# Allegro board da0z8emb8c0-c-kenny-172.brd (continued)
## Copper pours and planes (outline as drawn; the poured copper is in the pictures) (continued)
L_SPK+_1 on BOTTOM (solid shape): 116.31,22.34 116.41,22.29 116.52,22.27 116.54,22.27 116.62,22.25 116.65,22.17 116.65,20.41 116.37,20.13 116.37,19.55 116.22,19.4 115.34,19.4 115.22,19.52 115.22,20.3 115.91,20.99 115.91,22.23 116.02,22.34
L_SPK- on TOP (solid shape): 117.26,17.76 117.26,16.61 117.11,16.46 116.22,16.46 116.11,16.57 116.11,17.82 116.18,17.89 117.12,17.89
L_SPK- on IN2 (solid shape): 117.24,16.91 117.24,15.52 117.05,15.33 116.19,15.33 116.05,15.46 116.05,16.84 116.24,17.02 117.14,17.02
L_SPK- on IN2 (solid shape): 202.06,21.57 202.06,19.65 201.89,19.48 200.3,19.48 200.17,19.62 200.17,19.97 200.66,20.46 201.01,20.46 201.21,20.67 201.21,20.67 201.27,20.73 201.27,21.52 201.37,21.62 202,21.62
L_SPK-_1 on TOP (solid shape): 117.04,21.32 117.16,21.28 117.28,21.27 117.4,21.28 117.52,21.32 117.53,21.32 117.66,21.32 117.79,21.2 117.79,20.36 117.66,20.23 117.66,19.5 117.35,19.2 117.35,18.52 117.23,18.4 116.37,18.4 116.26,18.51 116.26,19.18 116.52,19.44 116.52,20.16 116.82,20.46 116.82,21.11 117.03,21.32
L_SPK-_1 on BOTTOM (solid shape): 117.08,22.33 117.18,22.29 117.28,22.27 117.39,22.29 117.49,22.33 117.5,22.34 117.61,22.34 117.66,22.29 117.66,19.49 117.47,19.29 116.69,19.29 116.56,19.42 116.56,19.97 116.94,20.35 116.94,22.26 117.02,22.34 117.07,22.34
LDO_3V3 on IN2 (solid shape): 17.79,13.02 17.79,11.85 17.56,11.63 15.31,11.63 13.99,12.94 13.99,14.31 14.19,14.51 16.3,14.51
MBCLK on TOP (solid shape): 103.97,22.21 103.97,21.65 103.8,21.47 103.21,21.47 103.01,21.27 102.13,21.27 102.01,21.4 102.01,21.98 102.05,22.03 102.6,22.03 102.84,22.27 102.84,22.54 103.09,22.79 103.39,22.79
MBCLK on BOTTOM (solid shape): 103.98,23.26 103.98,22.89 103.35,22.26 103.09,22.26 102.94,22.41 102.94,22.62 103.31,22.99 103.31,23.31 103.34,23.35 103.89,23.35
MBDATA on TOP (solid shape): 106.88,22.1 106.88,20.84 106.8,20.76 106.15,20.76 105.84,20.44 105.27,20.44 105.13,20.58 105.13,21.21 105.3,21.38 105.3,22.39 105.6,22.69 106.3,22.69
MVREFDA on TOP (solid shape): 118.97,101.49 118.97,101.36 118.96,101.34 118.78,101.13 118.72,100.87 118.74,100.73 118.79,100.59 118.8,100.56 118.79,100.53 118.69,100.44 117.87,100.44 117.87,100.44 117.87,101.16 117.88,101.2 117.92,101.21 118.24,101.21 118.53,101.5 118.96,101.5
MVREFDB on TOP (solid shape): 114.3,97.78 114.88,97.78 115.22,97.44 115.22,96.85 114.31,95.94 114.14,95.94 114.1,95.97 114.1,97.82 114.11,97.83 114.25,97.83
ODD_PRSNT#_C on BOTTOM (solid shape): 133.5,17.98 133.5,16.85 133.48,16.77 133.47,16.69 133.48,16.62 133.5,16.54 133.5,15.76 133.01,15.27 127.4,15.27 126.94,15.73 125.31,15.73 124.7,15.12 123.98,15.12 123.87,15.23 123.87,15.65 123.99,15.77 124.29,15.77 124.4,15.88 124.4,17.19 124.54,17.34 127.49,17.34 127.88,16.95 127.89,16.91 127.88,16.9 127.83,16.8 127.82,16.69 127.93,16.42 128.2,16.31 128.34,16.34 128.46,16.41 128.52,16.44 128.85,16.31 129.18,16.44 129.24,16.41 129.36,16.34 129.5,16.31 129.77,16.42 129.88,16.69 129.88,16.7 129.9,16.73 129.93,16.75 133.01,16.75 133.26,17 133.26,17.99 133.29,18.02 133.46,18.02
PBA_PWR on BOTTOM (solid shape): 52.56,22.72 52.56,20.76 52.34,20.53 50.79,20.53 49.95,21.37 49.95,22.62 50.11,22.78 51.2,22.78 51.29,22.69 51.29,22.24 51.42,22.11 52.03,22.11 52.13,22.21 52.13,22.69 52.26,22.82 52.46,22.82
PBA_PWR_C on BOTTOM (solid shape): 56.38,22.08 56.44,22.07 56.49,22.07 56.54,22.07 56.59,22.08 57.01,22.08 57.08,22.01 57.08,21.66 57.03,21.55 57.02,21.43 57.02,20.85 57.03,20.73 57.08,20.61 57.08,20.18 56.96,20.05 56.07,20.05 55.94,20.18 55.94,21.96 56.07,22.08
PBA_PWR_R on BOTTOM (solid shape): 53.4,22.44 53.4,22.13 53.55,21.98 55.46,21.98 55.64,21.8 55.64,20.15 55.39,19.91 55.37,19.9 55.34,19.9 55.26,19.92 55.18,19.93 55.02,19.9 54.87,19.82 53.58,19.82 53.35,19.59 52.77,19.59 52.73,19.61 52.72,19.65 52.72,20.56 52.82,20.66 52.82,22.74 52.83,22.78 52.87,22.8 53.05,22.8
R_SPK+ on TOP (solid shape): 120.22,17.75 120.22,16.53 120.13,16.44 118.85,16.44 118.7,16.59 118.7,17.79 118.8,17.89 120.08,17.89
R_SPK+ on IN2 (solid shape): 120.91,17.56 120.91,16.65 120.87,16.62 118.78,16.62 118.74,16.66 118.74,17.55 118.81,17.63 120.84,17.63
R_SPK+ on IN2 (solid shape): outline of 105 points within 195.67,19.39 200.96,22.04
R_SPK+_1 on TOP (solid shape): 119.02,21.35 119.16,21.29 119.31,21.27 119.38,21.27 119.46,21.25 119.49,21.17 119.49,20.81 119.53,20.65 119.62,20.51 119.93,20.2 119.93,20.18 120.03,19.9 120.29,19.75 120.31,19.73 120.31,18.51 120.25,18.44 119.12,18.44 119,18.55 119,19.24 119.16,19.4 119.16,19.93 118.93,20.16 118.93,21.32 118.97,21.36 119,21.36
R_SPK+_1 on BOTTOM (solid shape): 118.97,22.25 119.01,22.27 119.04,22.26 119.31,22.17 119.59,22.26 119.62,22.27 119.66,22.25 119.82,22.08 119.82,21.89 119.82,21.87 119.72,21.55 119.82,21.22 119.82,21.21 119.82,21.13 120.28,20.67 120.28,19.41 120.28,19.39 120.27,19.37 120.18,19.29 119.3,19.29 119.19,19.4 119.19,20.42 118.81,20.8 118.81,22.08
R_SPK- on TOP (solid shape): 118.54,17.83 118.54,16.6 118.42,16.48 117.52,16.48 117.4,16.6 117.4,17.8 117.49,17.89 118.47,17.89
R_SPK- on IN2 (solid shape): 118.53,18.87 118.53,16.63 118.52,16.62 117.48,16.62 117.4,16.7 117.4,18.85 117.53,18.99 118.41,18.99
R_SPK- on IN2 (solid shape): 202.46,23.76 202.46,22.05 202.35,21.94 201.64,21.94 201.34,22.25 201.34,22.86 200.81,23.39 200.81,24.1 201.07,24.36 201.86,24.36
R_SPK-_1 on TOP (solid shape): 118.05,21.32 118.17,21.28 118.3,21.27 118.42,21.28 118.54,21.32 118.55,21.32 118.68,21.2 118.68,20.02 118.94,19.77 118.94,19.47 118.72,19.25 118.72,18.54 118.58,18.4 117.77,18.4 117.66,18.51 117.66,19.28 117.8,19.42 117.8,20.21 117.92,20.32 117.92,21.2 118.04,21.32
R_SPK-_1 on BOTTOM (solid shape): 118.1,22.33 118.19,22.29 118.3,22.27 118.4,22.29 118.5,22.33 118.51,22.34 118.55,22.34 118.68,22.21 118.68,20.47 118.91,20.24 118.91,19.43 118.78,19.29 117.9,19.29 117.79,19.41 117.79,20.3 117.92,20.43 117.92,22.21 118.04,22.34 118.08,22.34
RING2 on BOTTOM (solid shape): 210.45,35.46 210.45,34.35 210.39,34.3 209.36,34.3 209.24,34.41 209.24,35.47 209.35,35.57 210.34,35.57
RING2 on BOTTOM (solid shape): 214.07,40.5 214.07,39.32 214.02,39.28 212.63,39.28 212.56,39.35 211.97,39.35 211.85,39.47 211.85,39.55 213.96,39.55 213.96,39.75 212.66,39.75 212.66,39.55 211.85,39.55 211.85,40.05 213.96,40.05 213.96,40.25 212.66,40.25 212.66,40.05 211.85,40.05 211.85,40.42 211.98,40.55 214.02,40.55
RING2 on BOTTOM (solid shape): 203.21,31.44 203.21,31.15 203.1,31.04 202.78,31.04 202.6,30.86 202.6,30.79 202.58,30.73 202.58,30.67 202.58,30.6 202.6,30.55 202.6,30.46 202.63,30.43 202.63,29.33 202.58,29.28 202.46,29.28 202.44,29.31 202.44,30.27 202.04,30.66 202.04,31.52 202.07,31.55 202.42,31.55 202.6,31.73 202.92,31.73
RING2 on IN1 (solid shape): outline of 282 points within 201.95,30.71 212.64,40.86
SENSEA on BOTTOM (solid shape): 200.8,32.31 200.89,32.21 200.89,31.85 200.66,31.62 200.66,30.84 200.98,30.53 200.98,30.51 201,30.39 201.04,30.28 201.04,29.31 200.97,29.24 200.89,29.24 200.19,29.94 200.19,30.28 200.13,30.59 199.95,30.85 199.77,31.03 199.77,31.97 199.77,31.97 199.77,32.28 199.8,32.31 200.8,32.31
SLEEVE on BOTTOM (solid shape): 210.49,34.04 210.49,33.25 210.37,33.13 209.4,33.13 209.29,33.23 209.29,34.12 209.3,34.14 210.4,34.14
SLEEVE on BOTTOM (solid shape): 212.41,39.04 213.99,39.04 214.02,39.01 214.02,38.75 212.66,38.75 212.66,38.55 214.02,38.55 214.02,38.25 212.66,38.25 212.66,38.05 214.02,38.05 214.02,37.82 213.95,37.75 212.52,37.75 212.29,37.97 212,37.97 211.88,38.1 211.88,39.02 211.95,39.09 212.36,39.09
SLEEVE on IN3 (solid shape): 204.57,30.84 204.57,29.55 204.4,29.38 202.83,29.38 202.7,29.52 202.7,30.75 202.86,30.91 204.5,30.91
SLEEVE on IN3 (solid shape): 212.59,39.02 212.59,38.06 212.51,37.98 211.54,37.98 211.5,37.94 210.93,37.94 210.69,38.18 210.69,38.84 210.96,39.12 212.5,39.12
SLEEVE on IN3 (solid shape): 209.19,34.33 209.23,34.28 209.28,34.24 209.38,34.14 210.57,34.14 210.62,34.09 210.62,33.39 210.27,33.03 209.3,33.03 209.14,33.2 208.56,33.2 208.4,33.03 207.46,33.03 207.2,33.29 207.2,34.64 207.5,34.94 208.58,34.94
TP_PWR_C on TOP (solid shape): 60.4,108.84 60.4,106.55 60.37,106.53 60.37,106.08 60.27,105.97 59.41,105.97 59.29,106.09 59.29,106.1 59.13,106.26 59.13,107.05 59.05,107.12 59.05,107.19 59.02,107.28 58.93,107.32 58.55,107.32 58.5,107.31 57.92,107.89 57.92,108.52 58.01,108.61 58.05,108.61 58.06,108.62 59.62,108.62 59.92,108.92 60.32,108.92
TP_PWR_C on BOTTOM (solid shape): 59.14,108.37 59.14,107.81 58.87,107.54 58.87,106.75 58.83,106.71 58.62,106.71 58.59,106.73 58.57,106.76 58.57,107.54 58.37,107.54 58.37,106.76 58.36,106.73 58.32,106.71 58.1,106.71 58.07,106.74 58.07,107.61 57.95,107.74 57.95,108.33 58.07,108.45 59.06,108.45
USBPWRD2 on TOP (solid shape): 215.62,30.41 215.62,29.84 215.69,29.78 215.69,27.86 215.61,27.78 214.22,27.78 214.1,27.9 214.1,30.44 214.16,30.5 215.53,30.5
USBPWRD2 on BOTTOM (solid shape): 214.54,30.56 214.96,30.56 215.16,30.36 215.16,28.02 212.62,25.48 211.77,25.48 211.49,25.2 211.49,24.66 211.21,24.38 211.2,24.38 210.86,24.04 210.67,24.04 210.43,23.8 210.43,22.56 210.36,22.49 209.73,22.49 209.66,22.56 209.66,25.05 209.9,25.28 209.9,28.14 209.91,28.18 209.92,28.23 209.93,28.28 209.93,28.33 209.92,28.39 209.91,28.44 209.9,28.47 209.9,28.55 213.96,28.55 213.96,28.75 212.66,28.75 212.66,28.55 209.9,28.55 209.9,28.9 210.05,29.05 213.96,29.05 213.96,29.25 212.66,29.25 212.66,29.05 210.05,29.05 210.08,29.08 210.42,29.08 210.58,29.08 211.72,29.08 211.93,29.28 211.93,29.55 213.96,29.55 213.96,29.75 212.66,29.75 212.66,29.55 211.93,29.55 211.93,30.05 213.96,30.05 213.96,30.25 212.66,30.25 212.66,30.05 211.93,30.05 211.93,30.08 211.93,30.27 212.21,30.55 213.96,30.55 213.96,30.75 212.66,30.75 212.66,30.55 212.21,30.55 212.27,30.61 212.3,30.62 212.35,30.65 212.4,30.68 212.44,30.73 212.48,30.77 212.5,30.83 212.51,30.85 212.69,31.02 214.08,31.02
VA on TOP (solid shape): outline of 178 points within 8.75,111.06 41.12,121.81
VA on IN1 (solid shape): outline of 124 points within 8.81,114.16 38.87,118.68
VA on IN2 (solid shape): outline of 124 points within 8.81,114.16 38.87,118.68
VA on SVCC (solid shape): 42.86,122.56 42.86,122.01 41.67,120.82 41.61,120.73 41.59,120.64 41.59,115.15 40.6,114.16 37,114.16 36.82,114.34 36.74,114.39 36.64,114.41 25.84,114.41 25.75,114.39 25.66,114.34 23.07,111.75 21,111.75 20.56,112.18 20.48,112.23 20.38,112.25 15.66,112.25 13.7,114.21 13.62,114.27 13.52,114.29 10.28,114.29 9.89,114.9 9.33,115.38 9.08,115.55 8.81,115.68 8.81,117.52 9.08,117.65 9.33,117.82 10.03,118.48 10.43,119.37 12.97,119.37 13.72,117.6 15.5,116.87 32.66,116.87 34.45,117.61 35.19,119.4 35.19,122.87 42.56,122.87
VA2 on TOP (solid shape): 46.12,119.93 46.12,119.49 45.69,119.06 45.52,119.06 45.52,115.58 45.3,115.36 43.59,115.36 43.37,115.43 43.14,115.36 40.93,115.36 40.78,115.51 40.78,119.01 40.85,119.08 43.33,119.08 43.57,119.32 44.21,119.32 44.38,119.49 44.38,120.26 44.55,120.43 45.62,120.43
VREFC_A0 on TOP (solid shape): 141.16,117.33 141.16,116.1 141.14,116.07 141.11,116.05 140.65,116.05 140.61,116.07 140.6,116.1 140.6,116.16 140.54,116.31 140.39,116.37 140.11,116.37 140.04,116.35 139.98,116.31 139.98,116.38 139.47,116.89 139.47,117.36 139.54,117.44 141.05,117.44
VREFC_A1 on BOTTOM (solid shape): 140.47,83.56 140.48,83.56 140.5,83.55 140.56,83.5 140.64,83.46 140.67,83.43 140.67,83.1 140.67,83.07 140.56,82.93 140.53,82.78 140.62,82.55 140.84,82.43 140.86,82.43 141.05,82.24 141.05,81.86 141.04,81.81 141.03,81.77 141.04,81.72 141.05,81.68 141.05,80.63 141.29,80.39 143.45,80.39 143.58,80.26 143.58,79.75 143.48,79.64 140.86,79.64 140.12,80.38 140.12,83.19 140.15,83.22 140.19,83.27 140.2,83.33 140.2,83.56 140.21,83.56
VREFD1_A0 on TOP (solid shape): 148.89,114.16 148.89,113.88 149.06,113.7 149.43,113.7 149.51,113.62 149.51,112.49 149.4,112.39 149.1,112.39 148.97,112.25 148.97,111.84 148.86,111.73 148.15,111.73 147.74,112.14 147.74,112.79 147.89,112.94 148.31,112.94 148.38,112.87 148.44,112.83 148.52,112.81 148.54,112.8 148.6,112.74 148.66,112.72 148.86,112.72 148.93,112.75 148.96,112.83 148.96,113.21 148.93,113.28 148.86,113.31 148.66,113.31 148.63,113.3 148.6,113.29 148.57,113.28 148.53,113.29 148.47,113.33 148.39,113.35 148.36,113.36 148.34,113.4 148.34,114.15 148.43,114.24 148.81,114.24
VREFD1_A0 on BOTTOM (solid shape): 146.88,113.16 146.9,113.15 146.92,113.14 147.18,113.02 147.45,113.14 147.47,113.15 147.49,113.16 148.11,113.16 148.28,113 148.28,112.51 148.16,112.39 146.85,112.39 146.55,112.69 146.55,113.05 146.67,113.16
VREFD1_A1 on BOTTOM (solid shape): 131.31,90.7 131.31,89.12 131.53,88.89 132.94,88.89 134.2,87.63 134.2,87.46 134.19,87.44 134.18,87.43 134.04,87.3 133.99,87.12 134.04,86.95 134.18,86.8 134.18,86.78 134.18,86.47 134.11,86.39 133.9,86.39 133.31,86.98 133.29,87.02 133.38,87.17 133.41,87.3 133.31,87.56 133.06,87.66 132.92,87.63 132.8,87.56 132.77,87.54 132.73,87.56 132.39,87.9 132.09,87.9 132.08,87.9 131.92,87.94 131.76,87.9 131.75,87.9 130.72,87.9 130.51,88.1 130.51,88.89 130.65,89.02 130.65,90.78 130.72,90.85 131.16,90.85
VREFD2_A0 on BOTTOM (solid shape): 131.01,114.28 131.01,114.16 131,114.15 131,113.24 131.61,112.63 132.48,112.63 132.55,112.6 132.69,112.28 132.93,112.18 133.19,112.29 133.29,112.54 133.28,112.62 133.25,112.7 133.24,112.71 133.25,112.75 133.67,113.16 134.09,113.16 134.17,113.08 134.17,112.79 134.17,112.78 134.09,112.65 134.07,112.52 134.07,112.47 134.08,112.42 134.07,112.39 133.36,111.68 130.73,111.68 130.22,112.19 130.22,112.54 130.33,112.65 130.33,114.31 130.38,114.36 130.93,114.36
VREFD2_A1 on BOTTOM (solid shape): 147.73,86.38 147.73,85.99 147.59,85.85 147.18,85.85 146.72,86.31 146.71,86.32 146.68,86.39 146.63,86.45 146.61,86.47 146.61,86.49 146.61,86.7 146.61,86.72 146.63,86.74 146.67,86.78 146.71,86.83 146.73,86.85 146.75,86.86 147.25,86.86
VREFD2_A1 on BOTTOM (solid shape): 147.73,80.91 147.73,80.21 147.68,80.11 147.66,80 147.67,79.93 147.69,79.86 147.69,79.83 147.68,79.81 147.64,79.76 146.97,79.76 146.84,79.9 145.09,79.9 145.01,79.99 145.01,80.39 145.12,80.51 146.87,80.51 146.94,80.58 146.94,80.9 147.04,81.01 147.64,81.01
VSTBY_FSPI on TOP (solid shape): 176.33,32.55 176.33,32.37 176.34,32.31 176.36,32.24 176.36,31.74 176.34,31.67 176.33,31.61 176.34,31.55 176.36,31.48 176.36,30.94 176.35,30.92 176.34,30.9 176.2,30.76 176.14,30.66 176.11,30.55 176.11,29.81 176.12,29.74 176.12,29.11 176.09,29.08 176.07,29.07 176.05,29.06 175.98,29.06 175.92,29.12 175.92,30.54 175.96,30.62 175.98,30.72 175.98,31.82 175.97,31.9 175.93,31.98 175.92,32 175.92,32.09 175.92,32.11 176.01,32.24 176.03,32.37 176.03,32.58 176.04,32.58 176.31,32.58
N17046941 on BOTTOM (solid shape): 105.74,23.24 105.74,20.79 105.69,20.74 105.08,20.74 104.99,20.84 104.99,23.22 105.11,23.34 105.64,23.34
N17047007 on TOP (solid shape): 51.03,118.5 52.49,118.5 52.58,118.41 52.58,115.3 51.63,114.35 50.07,114.35 49.99,114.28 45.92,114.28 45.88,114.29 45.87,114.33 45.87,118.81 45.97,118.9 50.63,118.9
N17047087 on TOP (solid shape): 119.96,29.63 119.96,27.42 119.72,27.19 116.38,27.19 116.13,27.44 116.13,28.54 116.58,28.98 116.58,29.67 116.83,29.93 119.65,29.93
N17047087 on BOTTOM (solid shape): 119.04,31.88 119.04,28.08 119.41,27.71 119.41,27.14 119.21,26.95 115.23,26.95 115.13,27 115.02,27.01 114.91,27 114.81,26.95 113.79,26.95 113.5,26.66 110.42,26.66 110.29,26.79 110.29,28.98 113.48,32.17 118.75,32.17
N17047425 on BOTTOM (solid shape): 104.72,23.28 104.72,21.22 104.26,20.75 103.19,20.75 103.12,20.82 103.12,22.06 103.16,22.1 103.43,22.1 104.19,22.86 104.19,23.26 104.27,23.34 104.66,23.34
N17047601 on TOP (solid shape): 122.46,29.64 122.46,29.12 122.27,28.93 120.37,28.93 120.31,28.99 120.31,29.75 120.43,29.88 122.23,29.88
N18867651 on TOP (solid shape): 151.06,28.3 151.79,28.3 152.31,27.78 152.99,27.78 153.51,28.3 154.19,28.3 154.22,28.27 154.22,26.76 153.57,26.12 149.88,26.12 149.54,26.45 149.54,28.31 149.67,28.43 150.93,28.43
N18867812 on TOP (solid shape): 20.72,30.83 20.72,29.93 21.04,29.62 21.54,29.62 21.61,29.55 21.61,28.79 21.57,28.75 20.91,28.75 20.85,28.69 19,28.69 18.65,29.04 18.65,30.74 18.82,30.91 20.64,30.91
N18867812 on BOTTOM (solid shape): 21.43,30.36 21.43,29.31 21.35,29.23 21,29.23 20.25,28.47 19.9,28.47 19.89,28.47 18.93,28.47 18.89,28.51 18.89,29.7 18.61,29.97 18.61,30.51 18.66,30.57 19.13,30.57 19.13,30.56 19.97,30.56 20.18,30.77 21.03,30.77
N26418322 on BOTTOM (solid shape): 133.87,47.86 133.87,46.81 134,46.67 136.56,46.67 136.69,46.8 136.69,47.37 137,47.69 137.77,47.69 137.87,47.59 137.87,46.74 135.78,44.65 135.78,41.2 136.14,40.84 136.84,40.84 138.05,39.64 138.05,38.57 137.95,38.47 131.02,38.47 130.86,38.64 130.01,38.64 129.74,38.91 129.74,43.35 129.16,43.93 128.74,43.93 128.54,44.13 128.54,47.8 128.72,47.99 133.74,47.99
N26418350 on TOP (solid shape): 144.45,43.15 144.54,43.08 144.65,43.04 144.67,43.04 145.39,42.32 145.61,42.32 145.64,42.31 145.8,42.11 146.01,42.05 146.22,42.11 146.38,42.31 146.41,42.32 146.8,42.32 147.08,42.04 147.08,41.11 146.86,40.89 145.62,40.89 145.32,41.19 144.87,41.19 144.7,41.02 144.7,40.39 144.64,40.33 140.96,40.33 140.87,40.41 140.87,43.19 141.81,44.12 143.47,44.12
N26418350 on BOTTOM (solid shape): 143.85,45.13 143.85,44.34 144.07,44.12 144.26,44.12 144.31,44.07 144.31,41.42 144.23,41.33 144.05,41.33 143.85,41.13 143.85,40.34 143.99,40.2 143.99,39.23 144.14,39.08 144.61,39.08 144.98,39.45 145.54,39.45 145.59,39.4 145.59,39.01 144.85,38.27 142.71,38.27 142.37,38.62 142.37,39.62 143.09,40.34 143.59,40.34 143.59,41.13 143.35,41.13 143.35,40.34 143.09,40.34 143.09,41.13 142.9,41.33 142.9,44 143.01,44.12 143.37,44.12 143.59,44.34 143.59,45.13 143.59,45.13 143.84,45.13
N28087213 on TOP (solid shape): 38.16,112.51 38.16,111.87 38.03,111.75 27.8,111.75 27.32,111.26 25.36,111.26 25.23,111.39 25.23,112.51 25.49,112.76 37.91,112.76
N28087213 on BOTTOM (solid shape): 25.87,112.61 25.87,111.64 24.74,110.79 23.44,110.14 20.81,109.08 18.86,109.08 18.48,109.46 18.48,110.73 19.75,112 20.03,112 20.74,111.29 21.42,110.93 21.8,110.93 23.36,111.71 23.96,112.13 24.62,112.79 25.69,112.79
N30442036 on TOP (solid shape): 21.08,27.35 21.59,27.35 21.61,27.33 21.61,26.24 21.77,26.09 21.77,25.33 21.66,25.21 19.68,25.21 19.09,25.81 19.09,26.39 19.22,26.53 19.75,26.53 19.93,26.7 19.93,26.72 19.94,26.74 19.98,26.81 20,26.89 20,27.07 20.08,27.16 20.59,27.16 20.79,27.36 21.08,27.36
N30442036 on BOTTOM (solid shape): 19.94,27.87 20.04,27.65 20.25,27.54 20.27,27.53 20.32,27.48 21.71,27.48 21.81,27.38 21.81,25.49 21.63,25.31 20.1,25.31 19.91,25.5 19.44,25.5 18.91,26.03 18.91,27.82 18.98,27.89 19.91,27.89
N30568332 on BOTTOM (solid shape): 48.44,20.51 48.44,20.03 48.53,19.94 50.02,19.94 50.09,19.87 50.09,18.59 50.1,18.58 50.1,18.37 50.5,17.97 51.66,17.97 51.92,17.71 51.92,16.5 51.79,16.37 47.85,16.37 47.69,16.53 47.69,16.89 47.45,17.12 47.45,17.17 47.46,17.18 47.46,17.61 47.31,17.75 46.33,17.75 46.33,17.76 46.02,18.07 46.02,18.58 46.01,18.6 43.68,18.6 43.63,18.66 43.63,19.08 43.73,19.18 46.26,19.18 46.51,18.94 48.04,18.94 48.1,19 48.1,19 48.23,19.13 48.23,19.58 47.7,20.1 46.61,20.1 46.61,20.1 46.61,20.97 46.61,20.97 47.98,20.97
N30568337 on BOTTOM (solid shape): 143.09,34 143.09,33.28 143.3,33.07 145.64,33.07 145.68,33.02 145.68,32.51 145.63,32.45 143.35,32.45 142.98,32.09 142.98,29.87 142.48,29.36 140.66,29.36 140.56,29.46 140.56,30.78 140.56,30.82 140.59,30.85 140.61,30.87 140.65,30.88 140.69,30.87 140.76,30.85 140.83,30.85 141.21,31.23 140.83,31.61 140.76,31.6 140.69,31.58 140.65,31.58 140.61,31.59 140.59,31.6 140.56,31.64 140.56,31.68 140.56,32.45 140.6,32.53 140.7,32.54 140.79,32.51 140.88,32.49 141.27,32.88 140.88,33.27 140.66,33.2 140.52,33.02 140.45,32.95 140.35,32.98 140.35,32.99 139.24,32.99 139.02,33.21 138.95,33.27 138.95,34.32 138.96,34.32 142.76,34.32
N30568472 on TOP (solid shape): 44.8,19.05 44.8,18.11 43.07,16.38 42.75,16.38 42.55,16.58 42.55,19.01 42.74,19.19 44.66,19.19
N31069510 on TOP (solid shape): outline of 128 points within 153.86,24.47 157.6,28.31
N40550359 on BOTTOM (solid shape): 110.68,124.65 111.22,124.65 111.37,124.51 111.37,124.05 111.24,123.92 106.78,123.92 106.76,123.94 106.76,124.12 106.85,124.21 109.6,124.21 110.1,124.7 110.63,124.7
N45198823 on TOP (solid shape): 63.15,125.5 63.15,122.38 63.12,122.34 63,122.22 62.3,122.22 61.99,122.53 61.99,123.06 61.49,123.57 61.49,124.34 61.39,124.45 58.99,124.45 58.88,124.55 58.88,125.65 59.1,125.87 62.78,125.87
N45198823 on BOTTOM (solid shape): 60.44,125.66 60.44,124.94 59.64,124.14 58.22,124.14 58.01,124.35 58.01,125.87 58.07,125.93 60.17,125.93
N47284656 on TOP (solid shape): 43.88,27.16 45.48,27.16 45.51,27.15 45.53,27.11 45.53,22.34 45.15,21.96 43.85,21.96 43.47,22.34 43.47,23.52 43.49,23.54 43.55,23.57 43.59,23.6 43.91,23.93 43.96,24 43.98,24.09 43.98,25.41 43.96,25.5 43.91,25.58 43.78,25.7 43.71,25.75 43.62,25.77 43.52,25.77 43.49,25.79 43.47,25.82 43.47,26.32 42.34,27.45 41.24,27.45 41.19,27.5 41.19,27.66 41.2,27.7 41.24,27.71 43.33,27.71
N47284687 on TOP (solid shape): 32.53,27.75 34.92,27.75 35.2,28.03 35.2,28.19 35.52,28.5 36.4,28.5 36.44,28.46 36.44,25.94 36.4,25.9 35.91,25.9 35.64,25.63 35.64,25.34 35.43,25.13 35.37,25.13 35.33,25.15 35.3,25.15 34.92,25.15 34.9,25.15 34.86,25.13 32.19,25.13 31.56,24.5 30.8,24.5 30.67,24.62 30.67,28.38 30.99,28.7 31.57,28.7
N48075617 on TOP (solid shape): 195.99,23.07 195.99,22.83 195.96,22.75 195.96,22.67 195.96,22.6 195.99,22.51 195.99,22.21 195.71,21.94 195.71,17.86 196.25,17.33 197.22,17.33 197.42,17.13 197.42,16.5 197.29,16.37 193.62,16.37 193.4,16.58 193.4,18.84 193.99,19.43 193.99,21.83 193.86,21.96 193.86,23.1 193.99,23.23 195.84,23.23
N48075627 on TOP (solid shape): outline of 120 points within 192.44,27.64 194.63,30.59
N48075629 on TOP (solid shape): 197.4,31.3 197.4,31.27 197.42,31.24 197.44,31.22 197.47,31.2 197.5,31.19 197.52,31.19 198.33,31.19 198.37,31.19 198.4,31.17 198.42,31.15 198.43,31.13 198.44,31.09 198.44,29.96 197.45,29.96 196.99,29.5 196.79,29.5 196.56,29.27 196.56,28.22 196.52,28.18 196.02,28.18 195.9,28.31 195.9,29.56 195.97,29.64 196,29.65 196.04,29.69 196.07,29.73 196.09,29.75 196.27,29.93 196.27,30.34 196.53,30.34 196.53,30.28 196.55,30.23 196.57,30.18 196.59,30.13 196.63,30.08 196.67,30.05 196.71,30.01 196.76,29.99 196.82,29.97 196.87,29.96 196.93,29.96 196.98,29.96 197.04,29.98 197.09,30 197.13,30.03 197.18,30.06 197.21,30.11 197.25,30.15 197.27,30.2 197.28,30.26 197.29,30.31 197.29,30.37 197.28,30.42 197.27,30.48 197.25,30.53 197.21,30.57 197.18,30.61 197.13,30.65 197.09,30.68 197.04,30.7 196.98,30.71 196.93,30.72 196.87,30.72 196.82,30.71 196.76,30.69 196.71,30.67 196.67,30.63 196.63,30.59 196.59,30.55 196.57,30.5 196.55,30.45 196.53,30.39 196.53,30.34 196.27,30.34 196.27,31.28 196.37,31.38 197.39,31.38
N48632675 on BOTTOM (solid shape): 18.19,39.73 18.19,37.46 18.02,37.29 18.02,37.28 17.94,37.2 17.94,35.72 17.92,35.7 17.58,35.7 17.53,35.75 17.53,38.33 17.41,38.45 17.41,39.05 17.42,39.06 17.45,39.14 17.46,39.23 17.45,39.32 17.42,39.4 17.41,39.41 17.41,39.66 17.45,39.7 17.49,39.71 17.51,39.7 17.61,39.65 17.71,39.63 17.85,39.66 17.99,39.75 18.01,39.75 18.17,39.75
N48758638 on TOP (solid shape): 147.02,66.98 147.02,63.45 146.91,63.35 143.59,63.35 143.54,63.39 143.54,67.15 143.62,67.22 146.78,67.22
N48758638 on BOTTOM (solid shape): 143.32,65.42 144.11,65.42 144.31,65.61 146.98,65.61 147.1,65.5 147.1,65.14 147.32,64.92 148.11,64.92 148.11,64.92 148.11,64.67 148.11,64.66 147.32,64.66 147.1,64.44 147.1,64.25 147.05,64.2 144.4,64.2 144.31,64.28 144.31,64.46 144.11,64.66 143.32,64.66 143.14,64.48 142.17,64.48 142,64.31 142,62.88 141.9,62.78 141.54,62.78 141.25,63.06 141.25,64.92 144.11,64.92 144.11,65.16 143.32,65.16 143.32,64.92 141.25,64.92 141.25,65.8 141.6,66.14 142.6,66.14
N48758645 on TOP (solid shape): 146.45,77.34 148.82,77.34 149.21,76.95 149.21,74.77 149.12,74.68 142.21,74.68 142.11,74.74 142.01,74.78 141.32,74.78 141.02,75.08 141.02,76.06 140.71,76.36 140.71,77.65 140.93,77.87 145.92,77.87
N48758645 on BOTTOM (solid shape): 149.03,77.9 149.03,77.47 149.28,77.22 149.8,77.22 149.96,77.06 149.96,74.09 149.59,73.71 142.6,73.71 142.39,73.92 142.39,74.75 142.15,75 140.35,75 140,75.35 140,76.98 140.26,77.24 143.14,77.24 143.74,77.84 147.85,77.84 148.01,78 148.92,78

Small or netless copper shapes (teardrops, artwork), in the pictures only: 119 on TOP, 81 on BOTTOM, 95 on IN1, 37 on IN2, 167 on IN3

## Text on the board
Ref Des/Silkscreen Bottom: Please do not print out the lines with 0.39mils/0.01mm in width | DA0Z8EMB8C0  REV:C | MODEL:Z8E
User.Comments: 16x35 | 30x32 | 33x37
Ref Des/Silkscreen Top: Please do not print out the lines with 0.39mils/0.01mm in width | DA0Z8EMB8C0  REV:C
User.8: 15' hall sensor | 14' hall sensor
User.9: 17' hall sensor board reserve | Dul Mic reserve | 17' ODD conn reserve | MBZAU001010 | 14' KB conn | 15' KB conn | MBZ8P003010
User.12: +VDD_18_S5 | GND | VA | +3V | +1.8V | +1.2VSUS | +VDD_18 | +3V_S5 | +VDDCR_SOC | +VGA_CORE | +VDD_08 | +0.95V | +VCC_CORE | +3VPCU | +5V | +3VPCU_EC | +5V_S5 | +3VLCD_CON | ADOGND
User.29: +1.2VSUS | GND | ADOGND
User.30: +1.2VSUS | GND | ADOGND
User.45: FIGURE | TYPE | Oblong | Rectangle | Circle | SIZE | 43.0x20.0 | 59.0x20.0 | 59.0x28.0 | 63.0x31.0 | 71.0x31.0 | 75.0x39.0 | 91.0x28.0 | 102.0x31.0 | 118.0x20.0 | 252.0x232.0 | 157.0x157.0 | 10.0 | 12.0 | 14.0 | 18.0 | 22.0 | 32.0 | 35.0 | 99.0 | 102.0 | 118.0 | 126.0 | 154.0 | 221.0 | 41.0 | 43.0 | 47.0 | 63.0 | 67.0 | 75.0 | DRILL CHART: TOP to BOTTOM | ALL UNITS ARE IN MILS | PLATED | NON-PLATED | ROTATION | 90.000 | 0.000 | - | QTY | 2 | 6 | 4 | 1 | 33 | 5200 | 9 | 13 | 409 | 40 | 10 | 19 | 18 | 8 | 3 | 5747 | TOTAL HOLES:
